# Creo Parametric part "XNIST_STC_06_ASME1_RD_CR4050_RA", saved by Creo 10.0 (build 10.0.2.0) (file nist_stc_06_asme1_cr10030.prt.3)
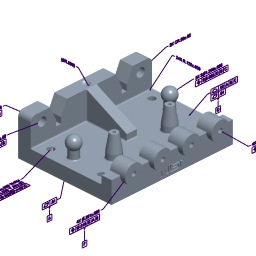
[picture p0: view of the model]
Units: Inch lbm Second (Pro/E Default); INCH, POUND, SECS

Created from: XNIST_FTC_06_ASME1_RD_CR4050_RA.PRT

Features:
  1. datum plane "RIGHT"
  2. datum plane "TOP"
  3. datum plane "FRONT"
  4. coordinate system
  5. protrusion
  6. datum plane "MIDPLANE"
  7. pattern
  8. protrusion
  9. protrusion
  10. protrusion
  11. protrusion
  12. cut
  13. curve
  14. curve
  15. datum plane "MIDPLANE_DTM_J"
  16. cut
  17. curve
  18. curve
  19. datum plane "MIDPLANE_DTM_K"
  20. datum plane "CONE_CENTERS"
  21. protrusion
  22. hole
  23. protrusion
  24. hole
  25. datum plane "SPHERE_CENTERS"
  26. protrusion
  27. protrusion
  28. pattern
  29. hole
  30. hole
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
Other named items: LOCAL_GROUP, LOCAL_GROUP_1, COPIED_GROUP_1, CONE_GAGE_CIRCLES, COPIED_GROUP, CONE_GAGE_HEIGHT, DRF_A, DRF_AB, CS2, DRF_DBC, CS4, DRF_D, CS6, CS7, CS8, DRF_F, DRF_DG, DRF_DH, DRF_DCJ, DRF_DCK, CS14, DRF_ABC, AD138, AD140, AD144, AD148, AD153, AD156, GP23, , AD212, GP26, AD213, GP27, AD214, GP28, AD215, GP29, AD216, GP30, AD217, GP31, AD218, AD219, RD8, GP32, DATUM_TAG_A, GP33, GP34, DATUM_TAG_D, NOTE_38, DATUM_TAG_F, DRF16, DRF17, AD222, GP35, DATUM_TAG_B, GP36, DATUM_TAG_C, GP37, GP38, GP39, DATUM_TAG_E, GP40, GP41, AD223, GP42, AD226, GP44, AD228, GP45, GP46, GP47, DRF18, MBD_A, MBD_B, MBD_C, ANNOT_LAYER_STATE0001, ANNOT_LAYER_STATE0002, ANNOT_LAYER_STATE0003

Layers: ALL_ANNOTATIONS, ALL_AXES, ALL_CSYS, ALL_CURVES, ALL_PLANES, ALL_POINTS, ALL_QUILTS, DEF_CSYS, DEF_PLANES

Notes: 2X 1.00 : 3.00 | 1.00 : 2.00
